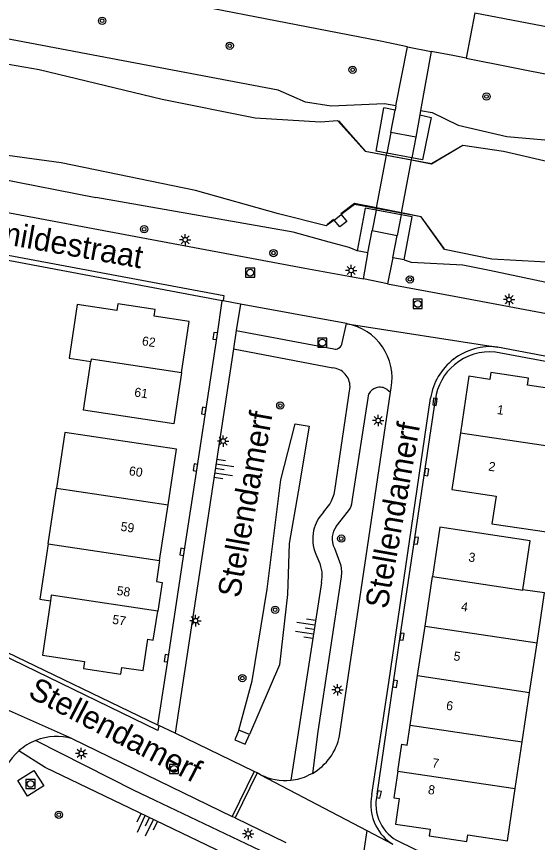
# Model space of a CAD drawing. Extents: x 124000 to 128010, y 398999 to 403000.
# Drawn here: x 126363.2 to 126420.5, y 399560.1 to 399650.9 of the extents above; entities that cross this region are included whole.
import ezdxf

# ---------------------------------------------------------------- set-up
doc = ezdxf.new("R2010")
doc.units = 0
for name, color, linetype in [('gg-anno-huisnummerreeks BGT', 7, 'Continuous'), ('gg-anno-openbare ruimte label', 7, 'Continuous'), ('gg-bbg-hoofdgebouw', 7, 'Continuous'), ('gg-bbg-tussenscheiding', 7, 'Continuous'), ('gg-knt-bovenkant onderkant talud', 7, 'Continuous'), ('gg-knt-verharding', 7, 'Continuous'), ('gg-knt-verharding niveau 01', 7, 'Continuous'), ('gg-kntw-beschoeiing', 7, 'Continuous'), ('gg-kntw-bovenkant insteek waterloop', 7, 'Continuous'), ('gg-kntw-waterlijn', 7, 'Continuous'), ('gg-kwrk-uitstroombak niveau min 01', 7, 'Continuous'), ('gt-grn-afwateringsgoot', 7, 'Continuous'), ('gt-grn-weggrens', 7, 'Continuous'), ('gt-symb-boom', 7, 'Continuous'), ('gt-symb-kolk', 7, 'Continuous'), ('gt-symb-lichtmast', 7, 'Continuous'), ('gt-symb-rioolschacht', 7, 'Continuous'), ('gt-symb-talud symbool', 7, 'Continuous'), ('gx-grn-maaiveld', 7, 'Continuous')]:
    doc.layers.add(name, color=color, linetype=linetype)

# ---------------------------------------------------------------- blocks, each defined once
blk = doc.blocks.new('gt0-KOLK')
at = {"layer": 'gt-symb-kolk'}
blk.add_lwpolyline([(0, 0), (0.375, 0), (0.375, 0.4), (-0.375, 0.4), (-0.375, 0), (0, 0)], dxfattribs=at)
blk = doc.blocks.new('gt0-LMAST')
at = {"layer": 'gt-symb-lichtmast'}
for p, q in [((-0.182, 0.173), (-0.447, 0.438)), ((-0.005, 0.246), (-0.005, 0.621)), ((0.172, 0.173), (0.437, 0.438)), ((-0.255, -0.004), (-0.63, -0.004)), ((-0.182, -0.181), (-0.447, -0.446)), ((-0.005, -0.254), (-0.005, -0.629)), ((0.437, -0.446), (0.172, -0.181)), ((0.245, -0.004), (0.62, -0.004))]:
    blk.add_line(p, q, dxfattribs=at)
blk.add_circle((-0.005, -0.004), 0.25, dxfattribs=at)
blk = doc.blocks.new('gt0-BOOM')
at = {"layer": 'gt-symb-boom'}
for radius in [0.4, 0.2]:
    blk.add_circle((0, 0), radius, dxfattribs=at)
blk = doc.blocks.new('gt0-RS')
at = {"layer": 'gt-symb-rioolschacht'}
blk.add_lwpolyline([(-0.5, -0.5), (0.5, -0.5), (0.5, 0.5), (-0.5, 0.5)], close=True, dxfattribs=at)
blk.add_circle((0, 0), 0.375, dxfattribs=at)
blk = doc.blocks.new('gt0-TALUD_1')
at = {"layer": 'gt-symb-talud symbool'}
for p, q in [((-1, -1), (-1, 0)), ((-0.5, -2), (-0.5, 0)), ((0, -1), (0, 0)), ((0.5, -2), (0.5, 0)), ((1, -1), (1, 0))]:
    blk.add_line(p, q, dxfattribs=at)

msp = doc.modelspace()

# ---------------------------------------------------------------- linework, layer by layer
at = {"layer": 'gg-bbg-hoofdgebouw'}
for p, q in [((126366.659, 399592.954), (126367.577, 399599.063)), ((126378.925, 399591.109), (126379.844, 399597.218)), ((126408.089, 399583.899), (126408.905, 399589.333)), ((126407.273, 399578.466), (126408.089, 399583.899)), ((126419.588, 399576.625), (126420.402, 399582.059)), ((126406.457, 399573.031), (126407.273, 399578.466)), ((126418.775, 399571.191), (126419.588, 399576.625)), ((126418.006, 399566.052), (126418.775, 399571.191))]:
    msp.add_line(p, q, dxfattribs=at)
for points in [[(126381.308, 399611.733), (126382.151, 399617.358), (126378.334, 399617.93), (126378.444, 399618.661), (126374.337, 399619.301), (126374.236, 399618.564), (126369.866, 399619.217), (126368.98, 399613.337), (126371.353, 399612.979)], [(126381.308, 399611.733), (126380.465, 399606.107), (126370.553, 399607.608), (126371.353, 399612.979)], [(126424.005, 399609.682), (126419.348, 399610.383), (126419.459, 399611.125), (126415.336, 399611.746), (126415.224, 399611.004), (126412.92, 399611.351), (126411.984, 399605.132)], [(126379.844, 399597.218), (126380.762, 399603.323), (126368.495, 399605.172), (126367.577, 399599.063)], [(126411.984, 399605.132), (126411.047, 399598.913), (126415.908, 399598.177), (126415.444, 399595.15), (126421.7, 399594.216)], [(126418.848, 399587.895), (126419.657, 399593.277), (126409.721, 399594.766), (126408.905, 399589.333)], [(126366.659, 399592.954), (126365.741, 399586.845), (126366.925, 399586.679)], [(126378.925, 399591.109), (126378.577, 399588.799), (126379.189, 399588.701), (126378.71, 399585.532)], [(126420.402, 399582.059), (126421.223, 399587.543), (126418.848, 399587.895)], [(126366.925, 399586.679), (126366.032, 399580.707), (126370.672, 399579.994), (126370.559, 399579.257), (126374.674, 399578.628), (126374.785, 399579.357), (126377.101, 399579.037), (126377.634, 399582.452), (126378.23, 399582.363), (126378.71, 399585.532)], [(126405.095, 399567.982), (126405.538, 399570.916), (126406.126, 399570.828), (126406.457, 399573.031)], [(126405.095, 399567.982), (126404.651, 399565.048), (126405.258, 399564.954), (126404.848, 399562.161), (126408.663, 399561.594), (126408.552, 399560.852), (126412.676, 399560.235), (126412.787, 399560.976), (126417.148, 399560.323), (126418.006, 399566.052)]]:
    msp.add_lwpolyline(points, dxfattribs=at)
at = {"layer": 'gg-bbg-tussenscheiding'}
for p, q in [((126411.984, 399605.132), (126423.078, 399603.461)), ((126367.577, 399599.063), (126379.844, 399597.218)), ((126366.659, 399592.954), (126378.925, 399591.109)), ((126408.089, 399583.899), (126420.402, 399582.059)), ((126407.273, 399578.466), (126419.588, 399576.625)), ((126406.457, 399573.031), (126418.775, 399571.191)), ((126405.095, 399567.982), (126418.006, 399566.052))]:
    msp.add_line(p, q, dxfattribs=at)
for points in [[(126381.308, 399611.733), (126371.389, 399613.219), (126371.353, 399612.979)], [(126408.905, 399589.333), (126418.841, 399587.847), (126418.848, 399587.895)], [(126378.71, 399585.532), (126367.017, 399587.291), (126366.925, 399586.679)]]:
    msp.add_lwpolyline(points, dxfattribs=at)
at = {"layer": 'gg-knt-bovenkant onderkant talud'}
msp.add_lwpolyline([(126387.632, 399572.481), (126389.092, 399577.895), (126390.75, 399587.966), (126392.261, 399599.983), (126393.819, 399606.105), (126395.34, 399605.859), (126394.147, 399598.656), (126393.145, 399592.967), (126392.977, 399587.383), (126392.094, 399579.653), (126388.784, 399571.99)], dxfattribs=at)
at = {"layer": 'gg-knt-verharding'}
for p, q in [((126412.617, 399646.276), (126442.093, 399640.494)), ((126406.642, 399635.328), (126403.903, 399635.856)), ((126405.468, 399629.09), (126402.721, 399629.597)), ((126385.796, 399619.625), (126335.328, 399629.125)), ((126387.797, 399619.279), (126385.889, 399619.632)), ((126387.797, 399619.279), (126387.34, 399616.376)), ((126399.467, 399617.122), (126387.797, 399619.279)), ((126398.979, 399615.026), (126399.467, 399617.122)), ((126399.544, 399617.108), (126399.467, 399617.122)), ((126387.34, 399616.376), (126387.024, 399614.342)), ((126387.34, 399616.376), (126398.061, 399614.348)), ((126387.024, 399614.342), (126380.618, 399572.128)), ((126387.024, 399614.342), (126397.949, 399612.28)), ((126398.69, 399571.849), (126404.312, 399609.583)), ((126400.119, 399597.832), (126401.929, 399609.421)), ((126403.922, 399609.899), (126404.312, 399609.583)), ((126404.312, 399609.583), (126404.385, 399610.071)), ((126396.089, 399591.79), (126396.413, 399591.043)), ((126396.696, 399588.7), (126393.346, 399566.969)), ((126378.741, 399573.034), (126358.786, 399582.601)), ((126378.85, 399572.981), (126378.741, 399573.034)), ((126380.618, 399572.128), (126378.85, 399572.981)), ((126369.334, 399571.531), (126386.904, 399562.985)), ((126389.3, 399567.93), (126380.618, 399572.128)), ((126390.011, 399567.578), (126389.627, 399567.772)), ((126395.715, 399567.723), (126395.301, 399567.51)), ((126387.23, 399562.826), (126392.778, 399560.127))]:
    msp.add_line(p, q, dxfattribs=at)
for points in [[(126403.903, 399635.856), (126402.711, 399636.086), (126403.575, 399640.816)], [(126408.756, 399639.773), (126407.819, 399635.101), (126406.642, 399635.328)], [(126333.627, 399630), (126355.561, 399625.892), (126385.974, 399620.224), (126385.889, 399619.632)], [(126402.721, 399629.597), (126401.512, 399629.82), (126400.635, 399625.131)], [(126405.784, 399624.127), (126406.665, 399628.869), (126405.468, 399629.09)], [(126378.741, 399573.034), (126379.859, 399580.339), (126381.607, 399592.023), (126383.045, 399601.297), (126385.23, 399615.738), (126385.796, 399619.625)], [(126385.889, 399619.632), (126385.799, 399619.649), (126385.796, 399619.625)], [(126471.852, 399603.492), (126465.908, 399604.637), (126415.834, 399613.989)], [(126495.524, 399599.645), (126476.675, 399603.199), (126439.344, 399610.167), (126432.851, 399611.367), (126416.068, 399614.558)], [(126396.939, 399596.412), (126397.625, 399597.311), (126397.817, 399597.662), (126397.975, 399598.027), (126398.096, 399598.4), (126398.182, 399598.781), (126399.847, 399610.207)], [(126402.239, 399565.395), (126404.095, 399577.692), (126408.695, 399608.948)], [(126402.825, 399565.449), (126405.364, 399582.767), (126409.225, 399608.799)], [(126398.338, 399594.833), (126399.696, 399596.566), (126399.855, 399596.824)], [(126398.124, 399592.459), (126398.798, 399590.671), (126398.884, 399590.285), (126398.92, 399589.799), (126398.879, 399589.318), (126396.308, 399572.313), (126395.715, 399567.723)], [(126378.85, 399572.981), (126378.741, 399572.434), (126358.719, 399582.145)], [(126365.323, 399571.344), (126376.079, 399565.893), (126390.703, 399558.927)], [(126390.678, 399556.69), (126366.326, 399568.368), (126363.448, 399570.19)], [(126363.322, 399566.923), (126365.09, 399568.051), (126366.182, 399566.34), (126364.414, 399565.212), (126363.322, 399566.923)], [(126405.306, 399560.191), (126421.407, 399552.396), (126424.333, 399550.907)]]:
    msp.add_lwpolyline(points, dxfattribs=at)
for centre, radius, start, end in [((126398.403, 399611.14), 6.076, 34.52967, 79.17803), ((126398.241, 399615.064), 0.739, 298.54702, 357.02173), ((126398.242, 399615.061), 0.736, 255.74817, 298.58124), ((126398.406, 399611.14), 6.073, 349.86185, 34.54433), ((126415.312, 399607.9), 6.7, 83.52006, 127.67065), ((126415.202, 399607.989), 6.033, 83.98302, 129.99734), ((126415.311, 399607.903), 6.698, 127.67615, 171.02399), ((126397.736, 399610.179), 2.112, 41.82129, 84.20974), ((126415.201, 399607.993), 6.03, 130.00939, 172.31364), ((126397.735, 399610.18), 2.112, 0.74518, 41.77987), ((126403.138, 399608.77), 1.373, 107.64907, 151.72001), ((126403.139, 399608.77), 1.373, 55.25408, 107.68439), ((126397.815, 399597.897), 2.305, 332.25965, 358.38756), ((126399.959, 399593.47), 4.216, 135.74462, 167.4042), ((126399.968, 399593.467), 4.226, 167.39562, 203.37476), ((126400.066, 399593.481), 2.194, 141.96145, 173.50818), ((126400.065, 399593.48), 2.193, 173.48377, 207.74465), ((126393.529, 399589.512), 3.266, 5.91385, 27.96789), ((126393.511, 399589.502), 3.285, 345.8742, 6.05388), ((126367.611, 399565.526), 6.252, 111.46959, 131.75224), ((126367.604, 399565.537), 6.239, 73.89746, 111.44114), ((126392.725, 399573.015), 6.078, 299.47099, 348.94299), ((126367.607, 399565.54), 6.239, 131.80852, 170.93992), ((126392.721, 399572.984), 6.047, 243.37249, 275.93014), ((126392.731, 399572.995), 6.058, 275.82949, 295.10684), ((126407.258, 399564.296), 5.138, 167.64512, 207.02364), ((126407.248, 399564.321), 4.565, 165.69676, 206.12922), ((126407.242, 399564.316), 4.557, 206.10696, 244.85778), ((126407.253, 399564.293), 5.133, 207.02001, 238.08539)]:
    msp.add_arc(centre, radius, start, end, dxfattribs=at)
at = {"layer": 'gg-knt-verharding niveau 01'}
for p, q in [((126404.322, 399638.126), (126403.903, 399635.856)), ((126407.074, 399637.597), (126404.322, 399638.126)), ((126407.074, 399637.597), (126406.642, 399635.328)), ((126402.721, 399629.597), (126402.293, 399627.346)), ((126405.468, 399629.09), (126405.032, 399626.806)), ((126402.293, 399627.346), (126405.032, 399626.806))]:
    msp.add_line(p, q, dxfattribs=at)
for points in [[(126402.721, 399629.597), (126402.764, 399629.828), (126403.859, 399635.624), (126403.903, 399635.856)], [(126405.468, 399629.09), (126405.506, 399629.29), (126406.6, 399635.104), (126406.642, 399635.328)]]:
    msp.add_lwpolyline(points, dxfattribs=at)
at = {"layer": 'gg-kntw-beschoeiing'}
for p, q in [((126398.585, 399639.397), (126401.512, 399636.069)), ((126408.801, 399634.687), (126412.004, 399636.594)), ((126401.512, 399636.069), (126403.859, 399635.624)), ((126403.859, 399635.624), (126406.6, 399635.104)), ((126406.6, 399635.104), (126408.801, 399634.687)), ((126398.041, 399628.573), (126397.371, 399628.01))]:
    msp.add_line(p, q, dxfattribs=at)
msp.add_lwpolyline([(126410.21, 399625.371), (126407.652, 399628.868), (126405.506, 399629.29), (126402.764, 399629.828), (126400.342, 399630.304), (126398.834, 399629.187)], dxfattribs=at)
at = {"layer": 'gg-kntw-bovenkant insteek waterloop'}
msp.add_line((126335.116, 399638.135), (126371.916, 399630.984), dxfattribs=at)
msp.add_lwpolyline([(126391.937, 399642.759), (126361.932, 399648.444), (126339.174, 399652.673)], dxfattribs=at)
at = {"layer": 'gg-kntw-waterlijn'}
msp.add_lwpolyline([(126337.649, 399646.946), (126341.882, 399649.685), (126346.087, 399648.936), (126353.857, 399647.105), (126365.681, 399645.05), (126379.205, 399641.792), (126389.405, 399639.738)], dxfattribs=at)
at = {"layer": 'gg-kwrk-uitstroombak niveau min 01'}
for p, q in [((126398.115, 399628.501), (126398.886, 399629.11)), ((126388.784, 399571.99), (126387.632, 399572.481))]:
    msp.add_line(p, q, dxfattribs=at)
for points in [[(126398.886, 399629.11), (126399.492, 399628.345), (126398.72, 399627.747), (126398.115, 399628.501)], [(126387.632, 399572.481), (126387.178, 399571.415), (126388.33, 399570.924), (126388.784, 399571.99)]]:
    msp.add_lwpolyline(points, dxfattribs=at)
at = {"layer": 'gt-grn-afwateringsgoot'}
for p, q in [((126389.3, 399567.93), (126386.904, 399562.985)), ((126389.627, 399567.772), (126387.23, 399562.826)), ((126389.627, 399567.772), (126389.3, 399567.93)), ((126387.23, 399562.826), (126386.904, 399562.985))]:
    msp.add_line(p, q, dxfattribs=at)
at = {"layer": 'gt-grn-weggrens'}
for p, q in [((126413.57, 399651.254), (126412.617, 399646.276)), ((126413.57, 399651.254), (126429.054, 399648.288)), ((126399.544, 399617.108), (126416.068, 399614.558)), ((126369.334, 399571.531), (126357.904, 399576.578)), ((126390.011, 399567.578), (126401.685, 399561.437)), ((126401.685, 399561.437), (126400.939, 399556.304)), ((126401.685, 399561.437), (126404.54, 399559.936))]:
    msp.add_line(p, q, dxfattribs=at)
at = {"layer": 'gx-grn-maaiveld'}
for p, q in [((126404.894, 399641.043), (126406.168, 399647.544)), ((126406.168, 399647.544), (126408.753, 399647.034)), ((126408.753, 399647.034), (126407.601, 399640.554)), ((126404.804, 399640.586), (126403.575, 399640.816)), ((126404.322, 399638.126), (126404.804, 399640.586)), ((126404.894, 399641.043), (126404.804, 399640.586)), ((126407.601, 399640.554), (126407.512, 399640.056)), ((126389.405, 399639.738), (126396.585, 399639.28)), ((126396.585, 399639.28), (126398.487, 399639.429)), ((126398.487, 399639.429), (126401.524, 399636.07)), ((126407.512, 399640.056), (126407.074, 399637.597)), ((126407.512, 399640.056), (126408.756, 399639.773)), ((126408.795, 399634.712), (126412.244, 399636.728)), ((126412.244, 399636.728), (126416.712, 399636.083)), ((126401.524, 399636.07), (126408.795, 399634.712)), ((126416.712, 399636.083), (126428.063, 399633.429)), ((126401.82, 399624.899), (126402.293, 399627.346)), ((126404.555, 399624.368), (126405.032, 399626.806)), ((126401.82, 399624.899), (126400.635, 399625.131)), ((126405.784, 399624.127), (126404.555, 399624.368)), ((126403.957, 399621.514), (126401.322, 399622.03))]:
    msp.add_line(p, q, dxfattribs=at)
for points in [[(126406.168, 399647.544), (126403.179, 399648.141), (126372.169, 399654.21)], [(126412.617, 399646.276), (126411.14, 399646.566), (126408.753, 399647.034)], [(126398.115, 399628.501), (126397.216, 399627.868), (126391.999, 399629.171), (126382.874, 399631.754), (126368.095, 399634.776), (126350.62, 399637.167), (126346.704, 399638.088), (126342.785, 399640.399), (126340.27, 399641.366), (126336.74, 399642.237), (126336.776, 399643.009)], [(126404.894, 399641.043), (126403.624, 399641.273), (126397.758, 399641.005), (126394.968, 399641.461), (126391.937, 399642.759)], [(126407.601, 399640.554), (126408.865, 399640.325), (126411.728, 399638.925), (126417.095, 399637.695), (126422.949, 399637.156)], [(126333.627, 399630), (126334.418, 399634.53), (126394.891, 399623.236), (126401.322, 399622.03)], [(126400.635, 399625.131), (126399.739, 399625.497), (126397.541, 399626.078), (126393.591, 399627.174), (126371.916, 399630.984)], [(126487.559, 399614.833), (126485.806, 399615.509), (126484.902, 399613.758), (126482.586, 399613.432), (126474.306, 399614.547), (126449.946, 399618.876), (126436.477, 399621.371), (126423.463, 399623.768), (126415.444, 399624.2), (126410.219, 399625.255), (126407.661, 399628.863), (126400.324, 399630.219), (126398.886, 399629.11)], [(126401.322, 399622.03), (126401.8, 399624.797), (126401.82, 399624.899)], [(126404.555, 399624.368), (126404.49, 399624.038), (126403.957, 399621.514)], [(126405.784, 399624.127), (126406.555, 399623.864), (126412.254, 399623.589), (126415.159, 399623.01), (126450.477, 399615.54)], [(126403.957, 399621.514), (126411.289, 399620.127), (126496.402, 399604.173)]]:
    msp.add_lwpolyline(points, dxfattribs=at)

# ---------------------------------------------------------------- block references
at = {"layer": 'gt-symb-boom'}
for p in [(126372.601, 399650.39), (126386.623, 399647.651), (126400.133, 399645.013), (126414.842, 399642.074), (126377.217, 399627.495), (126391.437, 399624.88), (126406.433, 399621.987), (126392.185, 399608.131), (126398.884, 399593.512), (126391.616, 399585.69), (126388.01, 399578.191), (126367.837, 399563.178)]:
    msp.add_blockref('gt0-BOOM', p, dxfattribs=at)
at = {"layer": 'gt-symb-kolk'}
for p, rotation in [((126385.23, 399615.738), 81.72381677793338), ((126409.382, 399608.521), 81.91897471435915), ((126383.977, 399607.511), 81.34034733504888), ((126383.045, 399601.297), 81.4624506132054), ((126408.057, 399600.843), -98.55351026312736), ((126406.926, 399593.317), -98.43938676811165), ((126381.607, 399592.023), 81.19309498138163), ((126405.364, 399582.767), -98.3571981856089), ((126379.859, 399580.339), 81.4875890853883), ((126404.603, 399577.583), -98.33324564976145), ((126402.825, 399565.449), -103.13192654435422)]:
    msp.add_blockref('gt0-KOLK', p, dxfattribs=dict(at, rotation=rotation))
at = {"layer": 'gt-symb-lichtmast'}
for p in [(126381.741, 399626.344), (126399.979, 399622.96), (126417.328, 399619.763), (126402.94, 399606.48), (126385.908, 399604.228), (126382.876, 399584.5), (126398.477, 399576.913), (126370.32, 399569.904), (126388.659, 399561.084)]:
    msp.add_blockref('gt0-LMAST', p, dxfattribs=at)
at = {"layer": 'gt-symb-rioolschacht'}
for p in [(126388.873, 399622.717), (126407.286, 399619.297), (126396.804, 399615.029), (126380.5, 399568.211), (126364.735, 399566.566)]:
    msp.add_blockref('gt0-RS', p, dxfattribs=at)
at = {"layer": 'gt-symb-talud symbool'}
for p, xscale, yscale, rotation in [((126385.031, 399601.207), 1.000310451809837, 1.000310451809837, 81.37577126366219), ((126395.902, 399583.551), 0.9996239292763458, 0.9996239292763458, -98.74616225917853), ((126377.791, 399562.87), 1.0001139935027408, 1.000113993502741, -25.591424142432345)]:
    msp.add_blockref('gt0-TALUD_1', p, dxfattribs=dict(at, xscale=xscale, yscale=yscale, rotation=rotation))

# ---------------------------------------------------------------- texts
at = {"layer": 'gg-anno-huisnummerreeks BGT'}
for s, rotation, p in [('62', 351.5, (126376.932, 399614.759)), ('61', 351.5, (126376.089, 399609.134)), ('1', 351.4, (126415.949, 399607.21)), ('60', 351.4, (126375.505, 399600.487)), ('2', 351.4, (126415.012, 399600.991)), ('59', 351.4, (126374.587, 399594.381)), ('3', 351.5, (126412.811, 399591.018)), ('58', 351.4, (126374.151, 399587.336)), ('4', 351.5, (126411.995, 399585.585)), ('57', 351.4, (126373.672, 399584.169)), ('5', 351.5, (126411.179, 399580.151)), ('6', 351.5, (126410.363, 399574.718)), ('7', 351.4, (126408.813, 399568.416)), ('8', 351.4, (126408.369, 399565.48))]:
    msp.add_text(s, height=1, rotation=rotation, dxfattribs=at).set_placement(p)
at = {"layer": 'gg-anno-openbare ruimte label'}
for s, rotation, p in [('Smildestraat', 349.9, (126358.541, 399626.443)), ('Stellendamerf', 79.9, (126387.735, 399586.917)), ('Stellendamerf', 79.9, (126403.95, 399585.707)), ('Stellendamerf', 332.5, (126364.334, 399576.174))]:
    msp.add_text(s, height=2.5, rotation=rotation, dxfattribs=at).set_placement(p)

doc.saveas('drawing.dxf')
